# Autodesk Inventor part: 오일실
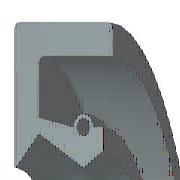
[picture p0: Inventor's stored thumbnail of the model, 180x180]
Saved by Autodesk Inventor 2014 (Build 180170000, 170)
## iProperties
IsCustomPart: 0
Created: 2014-10
Part Number: 오일실
Material: Rubber
Description: 오일-실
Document SubType Name: Modeling
Standard: KS B 2804
Designer: KYOUNG IL JANG
Standards Organization: KS
Language: ko-KR
Size Designation: D - 17 32 8
Categories: <MemberInstance><Categories><Category DisplayName="샤프트 부품" InternalName="7f7aeb1f-a693-4053-b835-cee3144e0d98" Mnemonic="SHFT"><Category DisplayName="실링" Intern
Density: 0.93 g/cm^3
Mass: 2.28027 g
Surface Area: 32.1224 cm^2
Volume: 2.45191 cm^3
Appearance: Rubber - Black - Version 1.1
Author: SeoGD™ [www.esajin.kr]
Revision Number: 1
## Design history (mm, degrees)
revolve "본체" stored, may be unused: angle "d17" = 90 deg
revolve "스프링1" stored, may be unused: angle "d18" = 90 deg
body "Solid1"
sketch "스케치1"
  geometry: L1 (0, 16)-(8, 16); L2 (8, 14.25)-(1.75, 14.25); L3 (1.75, 10.25)-(4.9, 8.5); L4 (4.9, 8.5)-(0, 8.5); L5 (0, 0)-(9.586, 0) reference; L6 (4.9, 8.5)-(6.3, 9.375); L7 (0, 18)-(0, -3) reference; L8 (-1.941, 0)-(11.507, 0) reference; L9 (4.2, 10.6)-(1.75, 11.21); L10 (1.75, 11.21)-(1.75, 14.25); L11 (0, 16)-(0, 8.588); L12 (4.9, 8.5)-(0, 8.5); L13 (1.75, 10.25)-(0.152, 8.528); L14 (8, 16)-(8, 14.25); L15 (5.6, 10.6)-(6.3, 10.6); L16 (6.3, 10.6)-(6.3, 9.375); C1 r 0.455 at (4.9, 10.6); A1 r 0.7 centre (4.9, 10.6) between (5.6, 10.6) and (4.2, 10.6); A2 r 0.088 centre (0.088, 8.588) between (0, 8.588) and (0.152, 8.528); 1 further point
  constraints: 28 end point, 5 horizontal alignment, 5 point on line, 4 point on circle, 4 vertical alignment, 3 centre point, 3 tangent, 2 collinear, 2 horizontal, 2 perpendicular, 1 coincident, 1 parallel
  dimensions: "d0" = 32 diameter of L1 L5 (= SD2); "d1" = 1.75 distance of L1.end L2.start (= SD); "d2" = 0.91 diameter of C1 (= SPDI); "d3" = 1.4 diameter of A1 (= SPDA); "d4" = 17 diameter of L3.end L5 (= NND); "d5" = 20.5 diameter of L3.start L5 (= TKDM); "d7" = 22.42 diameter of L9.end L5 (= TKDM + 0.24 x SWDT); "d8" = 1.75 distance between parallel lines of L11 L10 (= SD); "d9" = 4.9 distance from line of L11 C1.centre (= SPDST); "d10" = 21.2 diameter of C1.centre L5 (= HLDM); "d11" = 0.0875 radius of A2 (= 0.25 x LAB); "d12" = 6.3 distance between parallel lines of L11 L16 (= SDI); "d13" = 18.75 diameter of L6.end L5 (= ABDM); "d14" = 8 distance from line of L11 L1.end (= SWDT)
fillet "모깎기1" dims "d6" = 0.3 (= RR)
other parameters: "SD2" = 32 [user parameter; used in 1 equation term], "SWDT" = 8 [user parameter; used in 2 equation terms], "RR" = 0.3 [user parameter; used in 1 equation term], "SD" = 1.75 [user parameter; used in 2 equation terms], "NND" = 17 [user parameter; used in 1 equation term], "SPDA" = 1.4 [user parameter; used in 1 equation term], "SPDI" = 0.91 [user parameter; used in 1 equation term], "TKDM" = 20.5 [user parameter; used in 2 equation terms], "HLDM" = 21.2 [user parameter; used in 1 equation term], "ABDM" = 18.75 [user parameter; used in 1 equation term], "SDI" = 6.3 [user parameter; used in 1 equation term], "SPDST" = 4.9 [user parameter; used in 1 equation term], "LAB" = 0.35 [user parameter; used in 1 equation term], "d15" = 0, "d16" = 0, "d19" = 0
